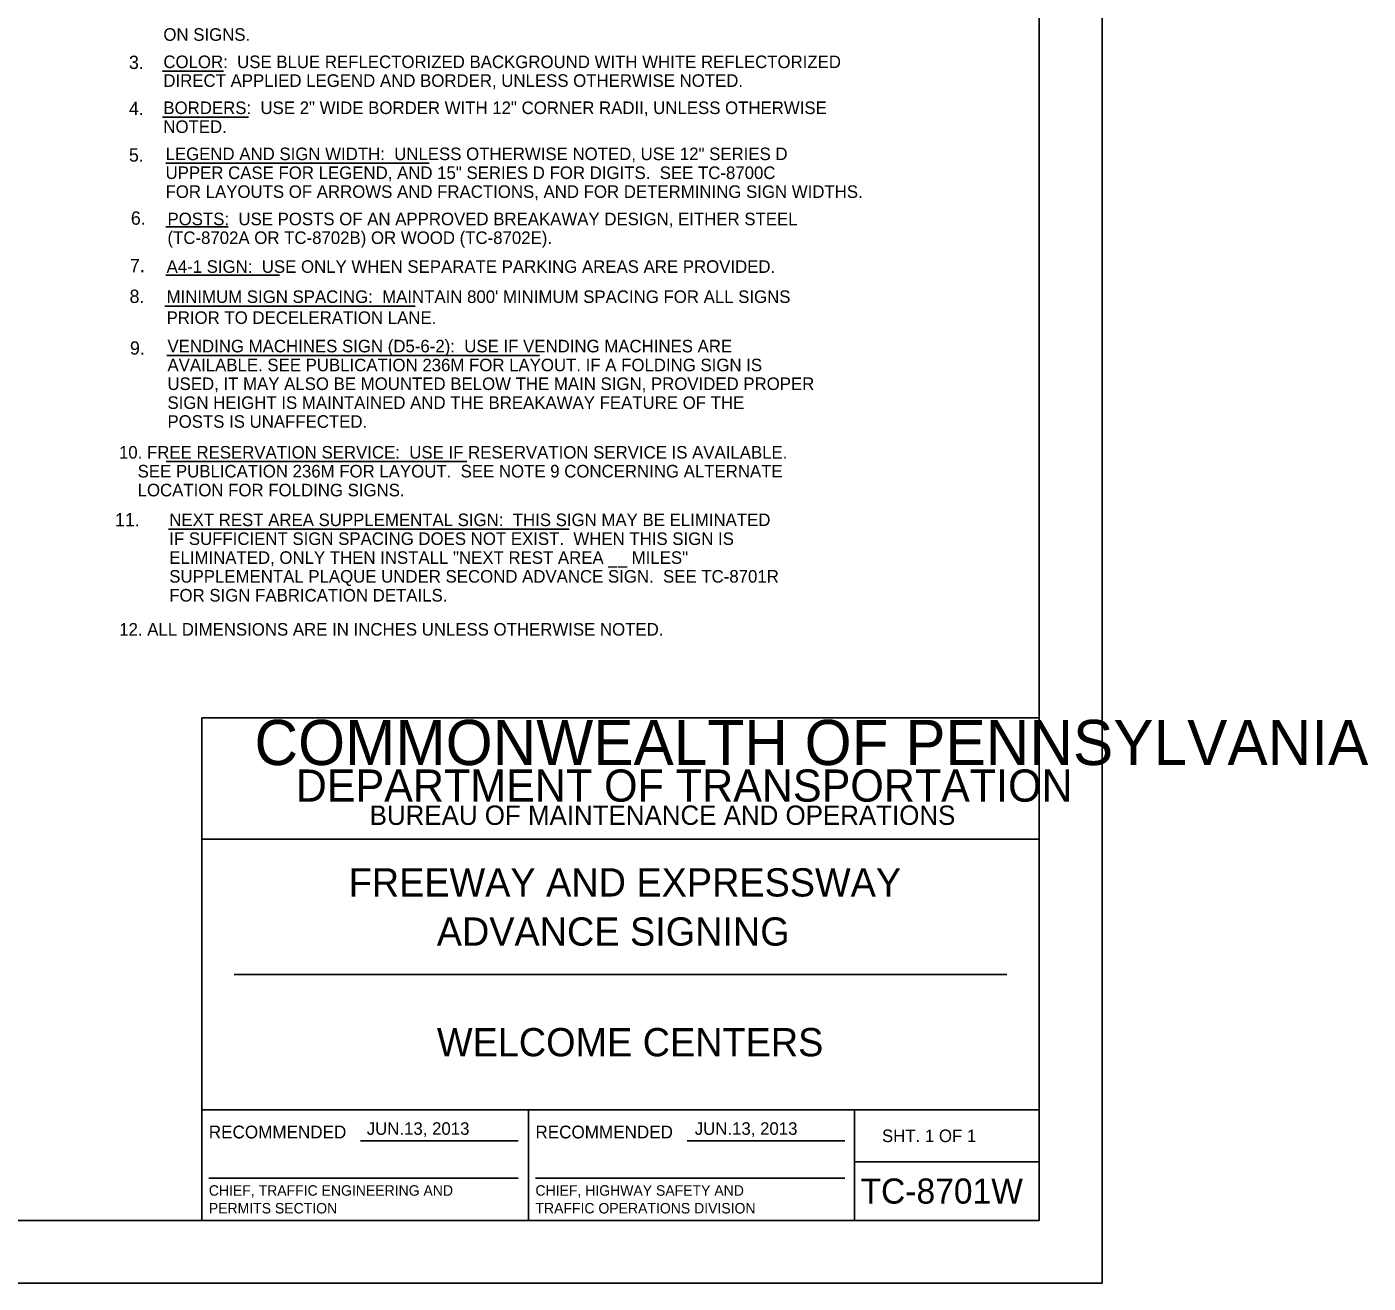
# Model space of a CAD drawing. Extents: x 2189973 to 2192941, y 2147557 to 2151454.
# Drawn here: x 2191890 to 2192941, y 2147557 to 2148541 of the extents above; entities that cross this region are included whole.
import ezdxf

# ---------------------------------------------------------------- set-up
doc = ezdxf.new("R2010")
doc.units = 0
for name, color, linetype in [('Default', 7, 'Continuous'), ('Level 1', 7, 'Continuous'), ('Level 2', 7, 'Continuous'), ('PLT-BNDY', 7, 'Continuous')]:
    doc.layers.add(name, color=color, linetype=linetype)

msp = doc.modelspace()

# ---------------------------------------------------------------- linework, layer by layer
at = {"layer": 'Default'}
for p, q in [((2192683.2, 2147606), (2192683.2, 2149456.4)), ((2191996.2, 2148506.4), (2192044.2, 2148506.4)), ((2191996.2, 2148470.3), (2192063.6, 2148470.3)), ((2191999, 2148434.1), (2192205.3, 2148434.1)), ((2191999, 2148384.3), (2192047.7, 2148384.3)), ((2191999, 2148346.6), (2192087.9, 2148346.6)), ((2191998.2, 2148322.1), (2192194.3, 2148322.1)), ((2191999.8, 2148283.5), (2192291.7, 2148283.5)), ((2191999.3, 2148200.6), (2192234.8, 2148200.6)), ((2192001, 2148147.6), (2192315, 2148147.6)), ((2192027, 2147606), (2192027, 2147999.7)), ((2192027, 2147999.7), (2192683.2, 2147999.7)), ((2192683.2, 2147904.5), (2192027, 2147904.5)), ((2192052.5, 2147798.5), (2192657.8, 2147798.5)), ((2192027, 2147692.5), (2192683.2, 2147692.5)), ((2192283, 2147692.5), (2192283, 2147606)), ((2192538.4, 2147606), (2192538.4, 2147692.5)), ((2192151.5, 2147668.2), (2192274.9, 2147668.2)), ((2192407.4, 2147668.2), (2192530.8, 2147668.2)), ((2192538.4, 2147651.9), (2192683.2, 2147651.9)), ((2192683.2, 2147606), (2190104.5, 2147606)), ((2190104.5, 2147606), (2192027, 2147606))]:
    msp.add_line(p, q, dxfattribs=at)
at = {"layer": 'Level 1'}
for p, q in [((2192032.6, 2147639), (2192274.9, 2147639)), ((2192288.5, 2147639), (2192530.8, 2147639))]:
    msp.add_line(p, q, dxfattribs=at)
at = {"layer": 'PLT-BNDY'}
msp.add_lwpolyline([(2189973.2, 2149505.6), (2192732.4, 2149505.6), (2192732.4, 2147556.8), (2189973.2, 2147556.8)], close=True, dxfattribs=at)

# ---------------------------------------------------------------- texts
at = {"layer": 'Default'}
for s, height, p in [('ON SIGNS.', 9.84, (2191997, 2148530.1)), ('COLOR:  USE BLUE REFLECTORIZED BACKGROUND WITH WHITE REFLECTORIZED', 9.842, (2191997, 2148508.7)), ('DIRECT APPLIED LEGEND AND BORDER, UNLESS OTHERWISE NOTED.', 9.842, (2191997, 2148494)), ('BORDERS:  USE 2" WIDE BORDER WITH 12" CORNER RADII, UNLESS OTHERWISE ', 9.842, (2191997, 2148472.7)), ('NOTED.', 9.84, (2191997, 2148457.9)), ('LEGEND AND SIGN WIDTH:  UNLESS OTHERWISE NOTED, USE 12" SERIES D', 9.842, (2191998.7, 2148436.6)), ('UPPER CASE FOR LEGEND, AND 15" SERIES D FOR DIGITS.  SEE TC-8700C', 9.842, (2191998.7, 2148421.8)), ('FOR LAYOUTS OF ARROWS AND FRACTIONS, AND FOR DETERMINING SIGN WIDTHS.', 9.842, (2191998.7, 2148407)), ('POSTS:  USE POSTS OF AN APPROVED BREAKAWAY DESIGN, EITHER STEEL', 9.842, (2192000.2, 2148385.6)), ('(TC-8702A OR TC-8702B) OR WOOD (TC-8702E).', 9.842, (2192000.2, 2148370.9)), ('A4-1 SIGN:  USE ONLY WHEN SEPARATE PARKING AREAS ARE PROVIDED.', 9.842, (2191999.5, 2148348.3)), ("MINIMUM SIGN SPACING:  MAINTAIN 800' MINIMUM SPACING FOR ALL SIGNS", 9.842, (2191999.5, 2148324.7)), ('PRIOR TO DECELERATION LANE.', 9.842, (2191999.5, 2148308.3)), ('VENDING MACHINES SIGN (D5-6-2):  USE IF VENDING MACHINES ARE', 9.842, (2192000.2, 2148286)), ('AVAILABLE. SEE PUBLICATION 236M FOR LAYOUT. IF A FOLDING SIGN IS', 9.842, (2192000.2, 2148271.2)), ('USED, IT MAY ALSO BE MOUNTED BELOW THE MAIN SIGN, PROVIDED PROPER', 9.842, (2192000.2, 2148256.5)), ('SIGN HEIGHT IS MAINTAINED AND THE BREAKAWAY FEATURE OF THE', 9.842, (2192000.2, 2148241.7)), ('POSTS IS UNAFFECTED.', 9.842, (2192000.2, 2148226.9)), ('10. FREE RESERVATION SERVICE:  USE IF RESERVATION SERVICE IS AVAILABLE.', 9.842, (2191962.2, 2148202.8)), ('    SEE PUBLICATION 236M FOR LAYOUT.  SEE NOTE 9 CONCERNING ALTERNATE', 9.842, (2191962.2, 2148188)), ('    LOCATION FOR FOLDING SIGNS.', 9.842, (2191962.2, 2148173.2)), ('11.', 10.44, (2191959.1, 2148149.7)), ('NEXT REST AREA SUPPLEMENTAL SIGN:  THIS SIGN MAY BE ELIMINATED', 9.842, (2192001.6, 2148149.9)), ('IF SUFFICIENT SIGN SPACING DOES NOT EXIST.  WHEN THIS SIGN IS', 9.842, (2192001.6, 2148135.1)), ('ELIMINATED, ONLY THEN INSTALL "NEXT REST AREA __ MILES" ', 9.842, (2192001.6, 2148120.3)), ('SUPPLEMENTAL PLAQUE UNDER SECOND ADVANCE SIGN.  SEE TC-8701R', 9.842, (2192001.6, 2148105.6)), ('FOR SIGN FABRICATION DETAILS.', 9.842, (2192001.6, 2148090.8)), ('12. ALL DIMENSIONS ARE IN INCHES UNLESS OTHERWISE NOTED.', 9.842, (2191962.4, 2148064.1)), ('COMMONWEALTH OF PENNSYLVANIA', 35.376, (2192068.4, 2147962.7)), ('DEPARTMENT OF TRANSPORTATION', 25.209, (2192100.7, 2147934)), ('BUREAU OF MAINTENANCE AND OPERATIONS', 15.175, (2192158.6, 2147915.8)), ('FREEWAY AND EXPRESSWAY', 22.146, (2192142.2, 2147859.7)), ('ADVANCE SIGNING', 22.146, (2192211.2, 2147821.2)), ('WELCOME CENTERS', 22.146, (2192211.3, 2147734.5)), ('RECOMMENDED', 10, (2192032.6, 2147670.2)), ('RECOMMENDED', 10, (2192288.5, 2147670.2)), ('SHT. 1 OF 1', 9.842, (2192560, 2147667.3)), ('TC-8701W', 19.68, (2192543.2, 2147619.1))]:
    msp.add_text(s, height=height, dxfattribs=at).set_placement(p)
for s, p in [('3.  ', (2191970, 2148508)), ('4.  ', (2191970, 2148471.9)), ('5.  ', (2191970, 2148435.4)), ('6.  ', (2191971.5, 2148386)), ('7.  ', (2191970.8, 2148348.8)), ('8.  ', (2191970.5, 2148324.7)), ('9.', (2191970.8, 2148284.2))]:
    msp.add_text(s, height=10.44, rotation=360, dxfattribs=at).set_placement(p)
at = {"layer": 'Level 1'}
for s, p in [('CHIEF, TRAFFIC ENGINEERING AND', (2192032.6, 2147625.3)), ('CHIEF, HIGHWAY SAFETY AND', (2192288.5, 2147625.3)), ('PERMITS SECTION', (2192032.6, 2147611.4)), ('TRAFFIC OPERATIONS DIVISION', (2192288.5, 2147611.4))]:
    msp.add_text(s, height=8.202, dxfattribs=at).set_placement(p)
at = {"layer": 'Level 2'}
for p in [(2192156.3, 2147673), (2192413.3, 2147673)]:
    msp.add_text('JUN.13, 2013', height=9.842, dxfattribs=at).set_placement(p)

doc.saveas('drawing.dxf')
